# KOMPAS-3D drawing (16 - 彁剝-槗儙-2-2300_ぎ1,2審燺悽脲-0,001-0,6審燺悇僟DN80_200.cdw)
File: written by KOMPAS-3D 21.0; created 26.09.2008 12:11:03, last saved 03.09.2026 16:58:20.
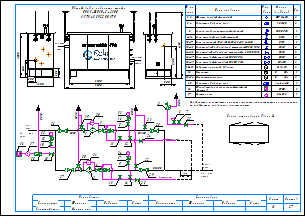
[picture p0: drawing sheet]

Sheets 1-2: A3, landscape

Document properties: Наименование: Макро:21; Автор: RaskoAdmin; Форматы листов документа: 2xA3; Полное имя файла: \\UR38nt01\Departments\КТО\КБ ПУРДГ\Заявки\Прайс-лист на типовые шкафы ГРПШ\ПРДГ_стандарт_20_03_2026\ПРДГ с РДГ(Н, В)\ПРДГ-ШУГО-2-2300_до1,2МПа_Рвых-0,001-0,6МПа_РДГ_DN80_200.cdw

Title block, sheet 1: Наименование: Пункт учета газа / ПУГ-Ш-400-Р / ЛГТИ.485922.001ТУ; designation: ЛГТИ.03.4411141; sheet number: 1; Количество листов документа: 2; organisation: ООО "ЭЛЬСТЕР Газэлектроника"; Форматы листов документа: A3; stored path: C:\Рабочие документы\Компас\ПУГ\Схема.cdw; Разработал: Устинов; Проверил: Кошкин; Утвердил: Кошкин
Title block, sheet 2: sheet number: 2; stored path: D:\Рабочие документы\Заявки\ПУРДГ\ПУРДГ-ШУЭО-2-100-Р 4411220.cdw; designation, second copy: ЛГТИ.03.4411141-

Views: Вид 1, Вид 2
Referenced files: wcvoit.frw
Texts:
  Normal
  Общий вид и габариты шкафа
  ПРДГ-ШУГО-2-2300
  DN200
  Выход газа
  DN80
  Вход газа
  logo-rasko-ge.png
  Вход
  газа
  PDI
  Выход
  Р=     кПа
  DN50
  DN25
  DN20
  Импульс DN20
  ≥5DN
  HYSWLongFangSong
  Р=       МПа
  № на
  схеме
  Усл.
  обозн.
  Марка
  (модель)
  Кол.
  Фильтр газовый фланцевый
  ФГ 16-80
  Регулятор давления газа
  РДГ-50
  Клапан предохранительный сбросной
  КПС DN20
  Кран шаровой газовый латунный
  DN15
  Кран кнопочный VE-РАСКО-НЗ-1,6-G1/2-М20
  Кран шаровой "под приварку" штуцерный DN20 PN16
  Кран шаровой "под приварку" штуцерный п/п DN20 PN16
  Кран шаровой фланцевый DN80 PN16
  Кран шаровой фланцевый DN200 PN16
  Индикатор перепада давления
  Delta 15
  Манометр
  Манометр-напоромер
  0...     МПа
  0...     кПа
  Обогреватель газогорелочный шкафной
  (Эльтон")
  Счетчик газа
  Venio-A-15
  ОГШН
  BK-G1,6
  Схема открывания дверей
  Предприятие изготовитель может заменять комплектующие на аналогичные,
  не ухудшающие заявленных характеристик.
  Должность
  Конструктор
  Фамилия
  Подпись
  Дата
  Согласовано
  Максимкин
  Лист
  Листов
  POLYLINE_STYLE_0.18_RGB_0_0_0
  POLYLINE_STYLE_0.50_RGB_0_0_0
  POLYLINE_STYLE_0.34_RGB_0_0_0
  PHANTOM_RGB_0_0_0_SC_1_THICK_0.18
  K5LT_THIN_RGB_0_0_0_THICK_0.18
  K5LT32769_RGB_0_0_0_THICK_0.18
  K5LT12_RGB_0_0_0_SC_1_THICK_0.18
  K5LT_DASHED_RGB_0_0_0_SC_1_THICK_0.18
  ACISOTGL_RGB_0_0_0_SC_0.8_THICK_0.25
  CONTINUOUS_RGB_0_127_31_THICK_0.3
  CONTINUOUS_RGB_0_0_255_THICK_0.35
  CONTINUOUS_RGB_255_0_0_THICK_0.35
  POLYLINE_STYLE_0.25_RGB_0_0_0
  CONTINUOUS_RGB_0_0_0_THICK_0.5
  POLYLINE_STYLE_0.35_RGB_0_0_255
  CONTINUOUS_RGB_0_0_0_THICK_0.4
  CONTINUOUS_RGB_0_0_0_THICK_0.35
  Без оформления
Dimensions and other numbers on the sheet: 1; 500; 1200; 305; 2000; 3600; 4130; 3300; 2; 3; 4; 5; 10; 27; 28; 29; 23; 8; 12; 19; 20; 21; 22; 25; 24; 30; 31; 15; 16; 32; 26; 6; 7; 11; 14; 13; 33; 9; 17; 34; 18; 35; 36; 37; 1, 2; 3, 4; 6-14; 15-17; 18-23; 24-25; 26-27; 28-29; 30-31; 33-34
